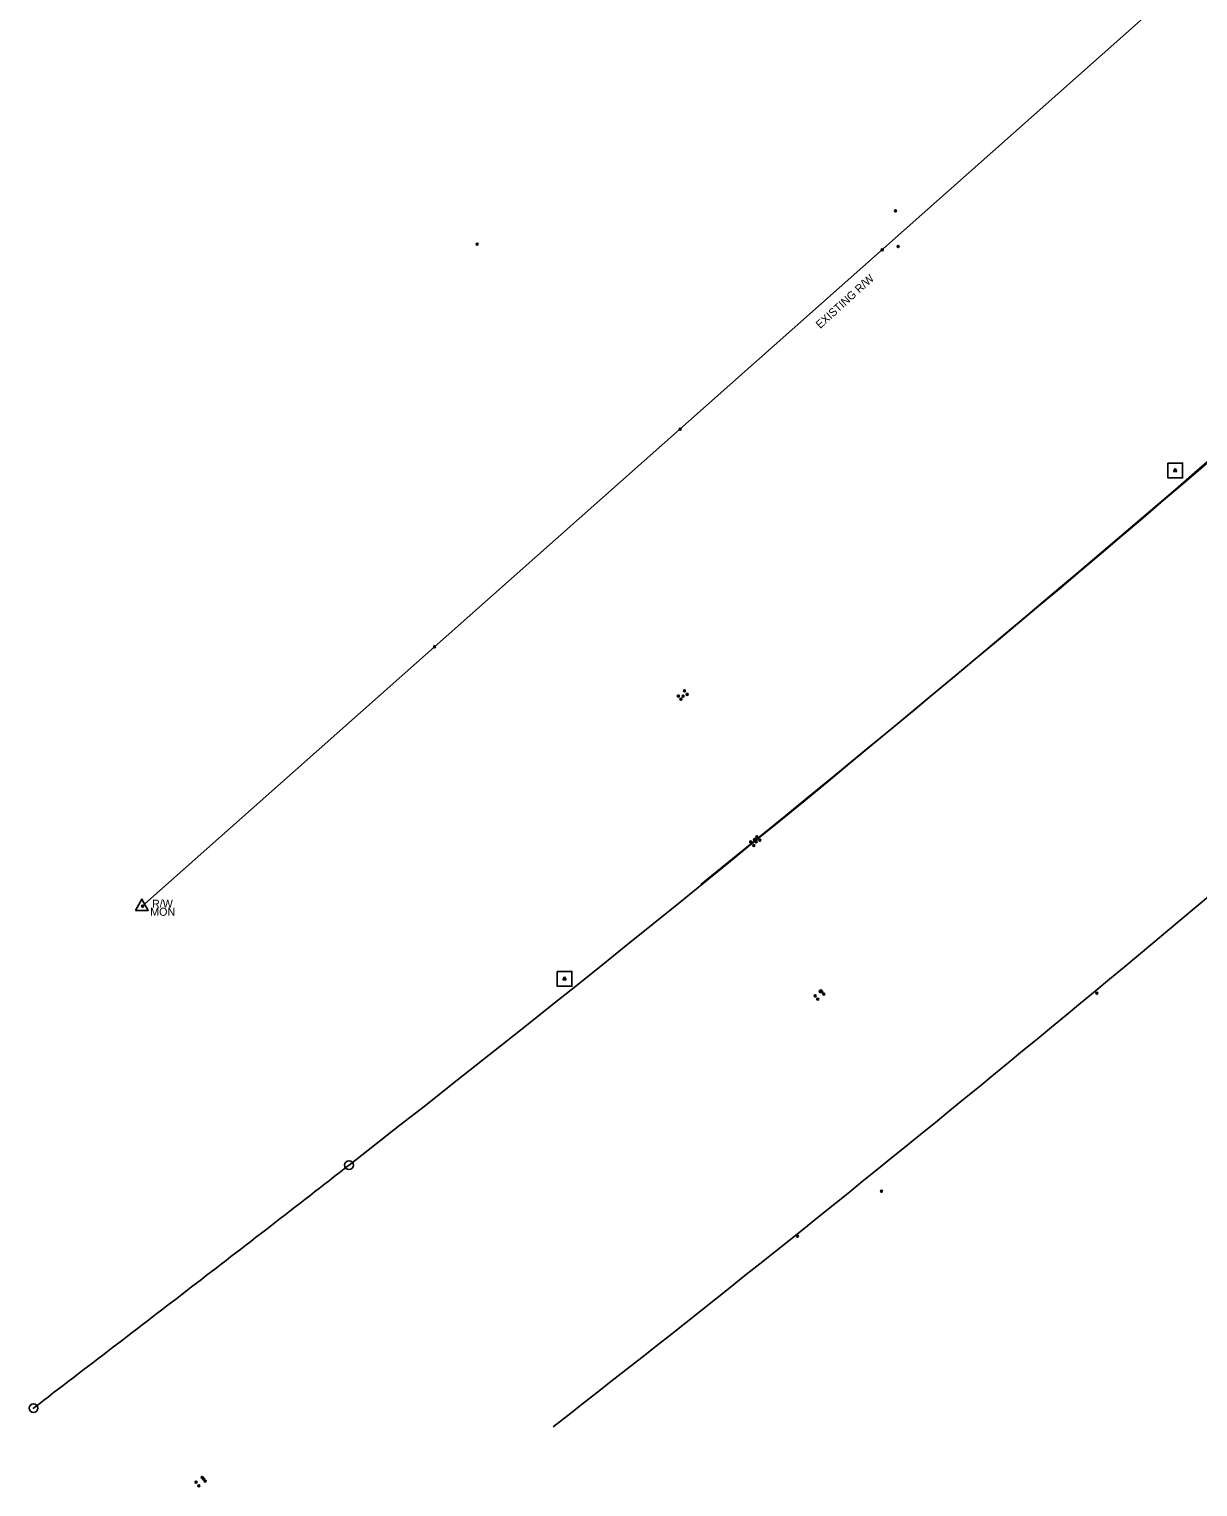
# Model space of a CAD drawing. Extents: x 1550153 to 1552579, y 809637 to 812160.
# Drawn here: x 1551130 to 1551717, y 810125 to 810857 of the extents above; entities that cross this region are included whole.
import ezdxf

# ---------------------------------------------------------------- set-up
doc = ezdxf.new("R2010")
doc.units = 0
for name, color, linetype in [('CTL Secondary Horizontal and Vertical CELL', 7, 'Continuous'), ('Default', 7, 'Continuous'), ('E_NCDOT_Horizontal_Alignment', 7, 'Continuous'), ('E_NCDOT_Horizontal_Alignment_Curve', 7, 'Continuous'), ('E_NCDOT_Horizontal_Alignment_Spiral', 7, 'Continuous'), ('E_NCDOT_Horizontal_Alignment_Tick_Label', 7, 'Continuous'), ('Exist Right of Way Line', 7, 'Continuous'), ('Exist Right of Way Line Text', 7, 'Continuous'), ('Exist Right of Way Monument CELL', 7, 'Continuous'), ('Exist Right of Way Monument Text', 7, 'Continuous')]:
    doc.layers.add(name, color=color, linetype=linetype)

# ---------------------------------------------------------------- blocks, each defined once
blk = doc.blocks.new('SurveyPointCell')
at = {"layer": 'Default'}
for p, q in [((-0.5, 0), (0.5, 0)), ((0, -0.5), (0, 0.5))]:
    blk.add_line(p, q, dxfattribs=at)
blk.add_circle((0, 0), 0.5, dxfattribs=at)
blk = doc.blocks.new('SurveyControlPointCell')
at = {"layer": 'Default'}
for p, q in [((-0.87, -0.5), (0, 1)), ((0, 1), (0.87, -0.5)), ((0.87, -0.5), (-0.87, -0.5))]:
    blk.add_line(p, q, dxfattribs=at)
blk.add_circle((0, 0), 0.5, dxfattribs=at)

msp = doc.modelspace()

# ---------------------------------------------------------------- linework, layer by layer
at = {"layer": 'CTL Secondary Horizontal and Vertical CELL'}
for p, q in [((1551705.21, 810635.48), (1551705.21, 810635.48)), ((1551705.21, 810635.48), (1551705.21, 810635.48)), ((1551398.47, 810380.18), (1551398.47, 810380.18)), ((1551398.48, 810380.18), (1551398.48, 810380.18))]:
    msp.add_line(p, q, dxfattribs=at)
for points in [[(1551701.53, 810639.18), (1551708.95, 810639.18), (1551708.95, 810631.76), (1551701.53, 810631.76)], [(1551701.54, 810639.18), (1551708.95, 810639.18), (1551708.95, 810631.75), (1551701.54, 810631.75)], [(1551394.79, 810383.88), (1551402.21, 810383.88), (1551402.21, 810376.46), (1551394.79, 810376.46)], [(1551394.81, 810383.88), (1551402.22, 810383.88), (1551402.22, 810376.45), (1551394.81, 810376.45)]]:
    msp.add_lwpolyline(points, close=True, dxfattribs=at)
at = {"layer": 'Default'}
for p, q in [((1551705.21, 810635.48), (1551705.21, 810635.48)), ((1551398.48, 810380.18), (1551398.48, 810380.18))]:
    msp.add_line(p, q, dxfattribs=at)
msp.add_arc((1544558.52, 818987.58), 11000, 308.905285, 313.48368, dxfattribs=at)
msp.add_arc((1544558.52, 818987.58), 11000, 308.905285, 313.48368, dxfattribs=at)
at = {"layer": 'E_NCDOT_Horizontal_Alignment'}
for centre, radius in [((1551290.22, 810286.57), 2.2), ((1551290.22, 810286.57), 0.0707), ((1551131.77, 810164.54), 2.2), ((1551131.77, 810164.54), 0.0707)]:
    msp.add_circle(centre, radius, dxfattribs=at)
at = {"layer": 'E_NCDOT_Horizontal_Alignment_Curve'}
msp.add_arc((1544245.73, 819324.67), 11459.16, 307.933611, 313.133611, dxfattribs=at)
msp.add_arc((1544245.73, 819324.67), 11459.16, 307.933611, 313.133611, dxfattribs=at)
at = {"layer": 'E_NCDOT_Horizontal_Alignment_Spiral'}
msp.add_open_spline([(1551131.77, 810164.54), (1551145, 810174.67), (1551171.47, 810194.93), (1551211.14, 810225.37), (1551250.74, 810255.88), (1551277.08, 810276.32), (1551290.22, 810286.57)], degree=3, dxfattribs=at)
msp.add_open_spline([(1551131.77, 810164.54), (1551145, 810174.67), (1551171.47, 810194.93), (1551211.14, 810225.37), (1551250.74, 810255.88), (1551277.08, 810276.32), (1551290.22, 810286.57)], degree=3, dxfattribs=at)
at = {"layer": 'E_NCDOT_Horizontal_Alignment_Tick_Label'}
msp.add_arc((1544558.52, 818987.58), 11000, 308.905285, 313.48368, dxfattribs=at)
at = {"layer": 'Exist Right of Way Line'}
msp.add_line((1551716.1, 810886.69), (1551186.17, 810416.44), dxfattribs=at)
msp.add_arc((1544245.55, 819324.92), 11626.16, 307.933611, 310.911902, dxfattribs=at)
at = {"layer": 'Exist Right of Way Monument CELL'}
msp.add_line((1551186.17, 810416.44), (1551186.17, 810416.44), dxfattribs=at)
msp.add_line((1551186.17, 810416.44), (1551186.17, 810416.44), dxfattribs=at)
msp.add_lwpolyline([(1551182.93, 810414.55), (1551186.18, 810420.19), (1551189.42, 810414.55)], close=True, dxfattribs=at)
msp.add_lwpolyline([(1551182.93, 810414.55), (1551186.18, 810420.19), (1551189.42, 810414.55)], close=True, dxfattribs=at)

# ---------------------------------------------------------------- block references
at = {"layer": 'Default'}
for name, p in [('SurveyPointCell', (1551564.72, 810765.95)), ('SurveyPointCell', (1551564.72, 810765.95)), ('SurveyPointCell', (1551354.57, 810749.1)), ('SurveyPointCell', (1551354.57, 810749.1)), ('SurveyPointCell', (1551558.11, 810746.33)), ('SurveyPointCell', (1551558.11, 810746.33)), ('SurveyPointCell', (1551566.05, 810747.97)), ('SurveyPointCell', (1551566.05, 810747.97)), ('SurveyPointCell', (1551456.62, 810656.3)), ('SurveyPointCell', (1551456.62, 810656.3)), ('SurveyControlPointCell', (1551705.21, 810635.48)), ('SurveyPointCell', (1551333.17, 810546.96)), ('SurveyPointCell', (1551333.17, 810546.96)), ('SurveyPointCell', (1551455.65, 810522.21)), ('SurveyPointCell', (1551455.65, 810522.21)), ('SurveyPointCell', (1551456.98, 810520.59)), ('SurveyPointCell', (1551456.98, 810520.59)), ('SurveyPointCell', (1551458.03, 810522.08)), ('SurveyPointCell', (1551458.03, 810522.08)), ('SurveyPointCell', (1551458.76, 810524.75)), ('SurveyPointCell', (1551458.76, 810524.75)), ('SurveyPointCell', (1551460.07, 810523.05)), ('SurveyPointCell', (1551460.07, 810523.05)), ('SurveyPointCell', (1551491.98, 810448.93)), ('SurveyPointCell', (1551491.98, 810448.93)), ('SurveyPointCell', (1551493.57, 810447.19)), ('SurveyPointCell', (1551493.57, 810447.19)), ('SurveyPointCell', (1551493.95, 810450.06)), ('SurveyPointCell', (1551493.95, 810450.06)), ('SurveyPointCell', (1551494.76, 810449.04)), ('SurveyPointCell', (1551494.76, 810449.04)), ('SurveyPointCell', (1551495.08, 810451.49)), ('SurveyPointCell', (1551495.08, 810451.49)), ('SurveyPointCell', (1551496.58, 810449.75)), ('SurveyPointCell', (1551496.58, 810449.75)), ('SurveyPointCell', (1551186.58, 810416.65)), ('SurveyPointCell', (1551186.58, 810416.65)), ('SurveyControlPointCell', (1551398.47, 810380.18)), ('SurveyPointCell', (1551526.93, 810373.73)), ('SurveyPointCell', (1551526.93, 810373.73)), ('SurveyPointCell', (1551527.22, 810374.17)), ('SurveyPointCell', (1551527.22, 810374.17)), ('SurveyPointCell', (1551527.65, 810373.58)), ('SurveyPointCell', (1551527.65, 810373.58)), ('SurveyPointCell', (1551528.69, 810372.51)), ('SurveyPointCell', (1551528.69, 810372.51)), ('SurveyPointCell', (1551665.88, 810372.94)), ('SurveyPointCell', (1551665.89, 810372.94)), ('SurveyPointCell', (1551524.33, 810371.67)), ('SurveyPointCell', (1551524.33, 810371.67)), ('SurveyPointCell', (1551524.37, 810371.57)), ('SurveyPointCell', (1551524.37, 810371.57)), ('SurveyPointCell', (1551525.64, 810369.99)), ('SurveyPointCell', (1551525.64, 810369.99)), ('SurveyPointCell', (1551557.7, 810273.5)), ('SurveyPointCell', (1551557.7, 810273.5)), ('SurveyPointCell', (1551515.48, 810250.92)), ('SurveyPointCell', (1551515.49, 810250.92)), ('SurveyPointCell', (1551213.38, 810127.3)), ('SurveyPointCell', (1551213.38, 810127.3)), ('SurveyPointCell', (1551214.78, 810125.5)), ('SurveyPointCell', (1551214.78, 810125.5)), ('SurveyPointCell', (1551216.55, 810129.75)), ('SurveyPointCell', (1551216.55, 810129.75)), ('SurveyPointCell', (1551217.26, 810128.82)), ('SurveyPointCell', (1551217.26, 810128.82)), ('SurveyPointCell', (1551217.93, 810127.93)), ('SurveyPointCell', (1551217.93, 810127.93))]:
    msp.add_blockref(name, p, dxfattribs=at)

# ---------------------------------------------------------------- texts
at = {"layer": 'Exist Right of Way Line Text'}
msp.add_text('EXISTING R/W', height=4.02, rotation=42.26373, dxfattribs=at).set_placement((1551526.9, 810706.49))
at = {"layer": 'Exist Right of Way Monument Text'}
for s, p in [('R/W', (1551191.27, 810415.88)), ('MON', (1551190.37, 810411.83))]:
    msp.add_text(s, height=4.02, dxfattribs=at).set_placement(p)

doc.saveas('drawing.dxf')
